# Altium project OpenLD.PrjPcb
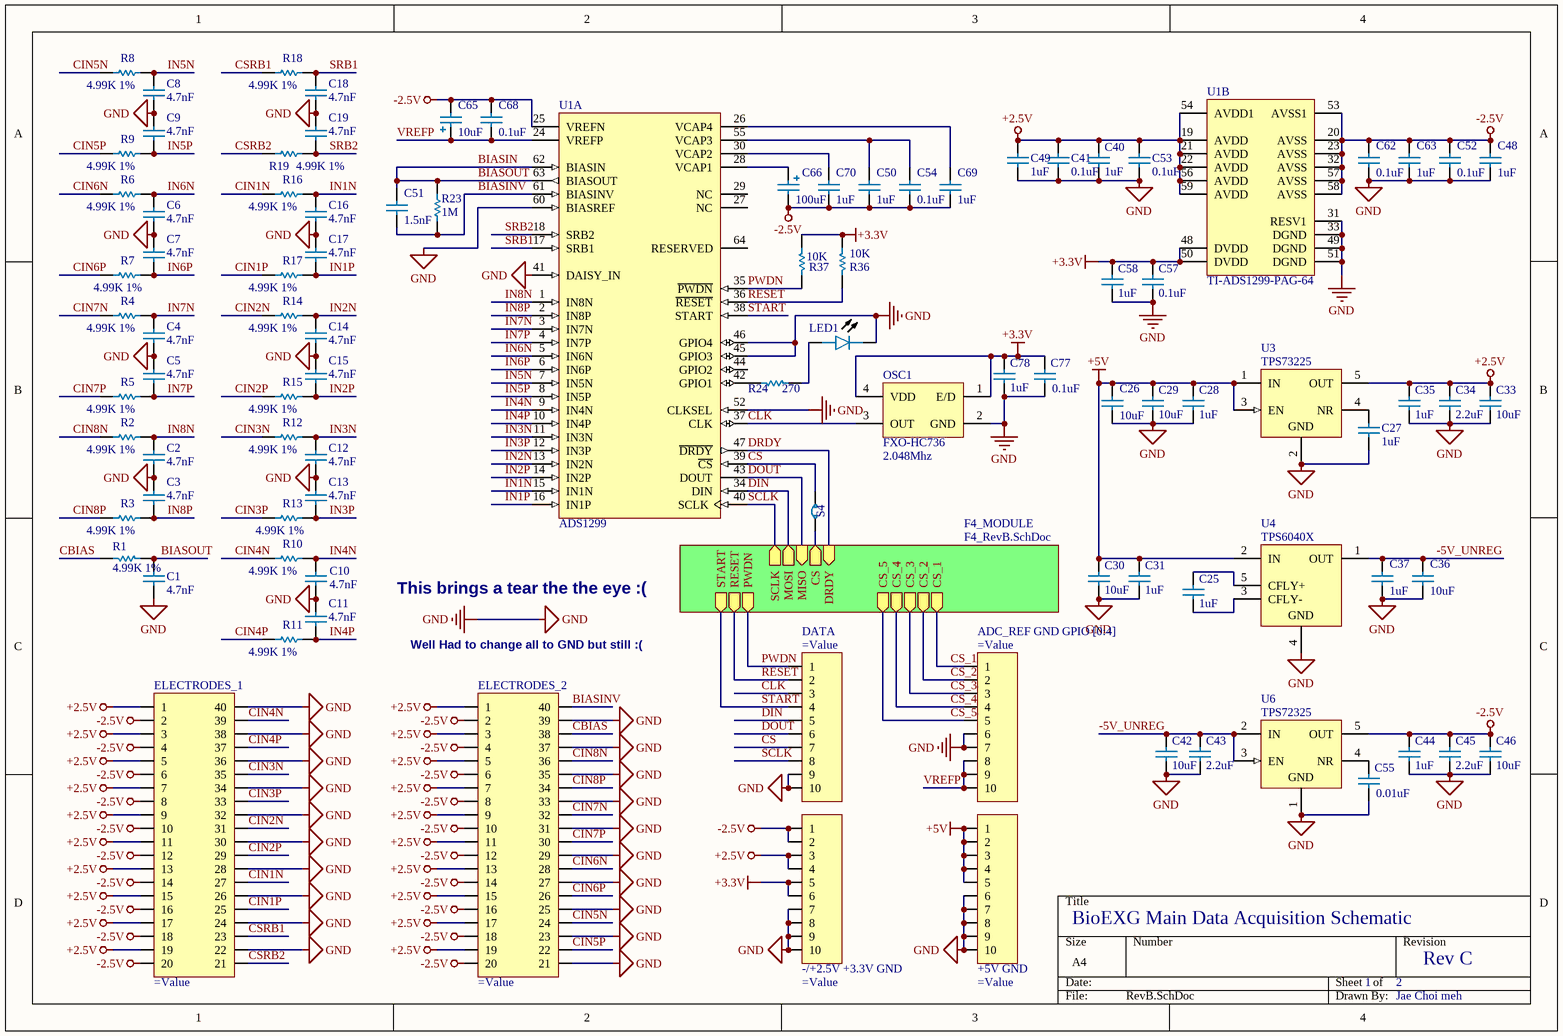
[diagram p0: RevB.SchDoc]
2 sheets, 147 parts. Net scope: hierarchical (ports join the sheet entries above them; power ports are global).
Board file: RevC.PcbDoc
Sheets:
  RevB.SchDoc
    F4_MODULE = F4_RevB.SchDoc

## Sheet RevB.SchDoc
size A4

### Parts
+5V_GND  (no value)  [M52-10]
-/+2.5V_+3.3V_GND  (no value)  [M52-10]
ADC_REF_GND_GPIO_[0:4]  (no value)  [M52-10]
C1  4.7nF  [C0603]
C2  4.7nF  [C0603]
C3  4.7nF  [C0603]
C4  4.7nF  [C0603]
C5  4.7nF  [C0603]
C6  4.7nF  [C0603]
C7  4.7nF  [C0603]
C8  4.7nF  [C0603]
C9  4.7nF  [C0603]
C10  4.7nF  [C0603]
C11  4.7nF  [C0603]
C12  4.7nF  [C0603]
C13  4.7nF  [C0603]
C14  4.7nF  [C0603]
C15  4.7nF  [C0603]
C16  4.7nF  [C0603]
C17  4.7nF  [C0603]
C18  4.7nF  [C0603]
C19  4.7nF  [C0603]
C25  1uF  [C0603]
C26  10uF  [C0603]
C27  1uF  [C0603]
C28  1uF  [C0603]
C29  10uF  [C0603]
C30  10uF  [C0603]
C31  1uF  [C0603]
C33  10uF  [C0603]
C34  2.2uF  [C0603]
C35  1uF  [C0603]
C36  10uF  [C0603]
C37  1uF  [C0603]
C40  1uF  [C0603]
C41  0.1uF  [C0603]
C42  10uF  [C0603]
C43  2.2uF  [C0603]
C44  1uF  [C0603]
C45  2.2uF  [C0603]
C46  10uF  [C0603]
C48  1uF  [C0603]
C49  1uF  [C0603]
C50  1uF  [C0603]
C51  1.5nF  [C0603]
C52  0.1uF  [C0603]
C53  0.1uF  [C0603]
C54  0.1uF  [C0603]
C55  0.01uF  [C0603]
C57  0.1uF  [C0603]
C58  1uF  [C0603]
C62  0.1uF  [C0603]
C63  1uF  [C0603]
C65  10uF  [TCAXM8R]
C66  100uF  [TCAXM8R]
C68  0.1uF  [C0603]
C69  1uF  [C0603]
C70  1uF  [C0603]
C77  0.1uF  [C0603]
C78  1uF  [C0603]
DATA  (no value)  [M52-10]
ELECTRODES_1  (no value)  [M50-40]
ELECTRODES_2  (no value)  [M50-40]
LED1  LSTS0603  [LITEON_LED_0603]  (value not drawn)
OSC1  FXO-HC736  value 2.048Mhz  [HC73]
R1  4.99K 1%  [ERA3A]
R2  4.99K 1%  [ERA3A]
R3  4.99K 1%  [ERA3A]
R4  4.99K 1%  [ERA3A]
R5  4.99K 1%  [ERA3A]
R6  4.99K 1%  [ERA3A]
R7  4.99K 1%  [ERA3A]
R8  4.99K 1%  [ERA3A]
R9  4.99K 1%  [ERA3A]
R10  4.99K 1%  [ERA3A]
R11  4.99K 1%  [ERA3A]
R12  4.99K 1%  [ERA3A]
R13  4.99K 1%  [ERA3A]
R14  4.99K 1%  [ERA3A]
R15  4.99K 1%  [ERA3A]
R16  4.99K 1%  [ERA3A]
R17  4.99K 1%  [ERA3A]
R18  4.99K 1%  [ERA3A]
R19  4.99K 1%  [ERA3A]
R23  1M  [ERA6A]
R24  270  [ERA3A]
R36  10K  [ERA3A]
R37  10K  [ERA3A]
S4  (no value)  [JUMPER]
U1  ADS1299  [TI-PAG64_N]  (parts A,B of 2)
U3  TPS73225  [TI-DBV5_N]
U4  TPS6040X  [TI-DBV5_N]
U6  TPS72325  [TI-DBV5_N]

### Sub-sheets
F4_MODULE = F4_RevB.SchDoc: PWDN (out), RESET (out), START (out), CS_5 (out), CS_4 (out), CS_3 (out), CS_2 (out), CS_1 (out), DRDY (in), CS (out), MISO (in), MOSI (out), SCLK (out)

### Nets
+2.5V: -/+2.5V_+3.3V_GND.3 -/+2.5V_+3.3V_GND.4 C33.2 C34.2 C35.2 C40.2 C41.1 C49.1 C53.1 ELECTRODES_1.1 ELECTRODES_1.3 ELECTRODES_1.5 ELECTRODES_1.7 ELECTRODES_1.9 ELECTRODES_1.11 ELECTRODES_1.13 ELECTRODES_1.15 ELECTRODES_1.17 ELECTRODES_1.19 ELECTRODES_2.1 ELECTRODES_2.3 ELECTRODES_2.5 ELECTRODES_2.7 ELECTRODES_2.9 ELECTRODES_2.11 ELECTRODES_2.13 ELECTRODES_2.15 ELECTRODES_2.17 ELECTRODES_2.19 U1.19(AVDD) U1.21(AVDD) U1.22(AVDD) U1.54(AVDD1) U1.56(AVDD) U1.59(AVDD) U3.5(OUT)
+3.3V: -/+2.5V_+3.3V_GND.5 -/+2.5V_+3.3V_GND.6 C57.2 C58.2 C77.2 C78.2 OSC1.1(E/D) OSC1.4(VDD) R36.2 R37.2 U1.48(DVDD) U1.50(DVDD)
+5V: +5V_GND.1 +5V_GND.2 +5V_GND.3 +5V_GND.4 +5V_GND.5 C26.1 C28.2 C29.2 C30.2 C31.2 U3.1(IN) U3.3(EN) U4.2(IN)
-2.5V: -/+2.5V_+3.3V_GND.1 -/+2.5V_+3.3V_GND.2 C44.2 C45.2 C46.2 C48.1 C50.2 C52.1 C54.2 C62.1 C63.1 C65.2 C66.2 C68.2 C69.2 C70.2 ELECTRODES_1.2 ELECTRODES_1.4 ELECTRODES_1.6 ELECTRODES_1.8 ELECTRODES_1.10 ELECTRODES_1.12 ELECTRODES_1.14 ELECTRODES_1.16 ELECTRODES_1.18 ELECTRODES_1.20 ELECTRODES_2.2 ELECTRODES_2.4 ELECTRODES_2.6 ELECTRODES_2.8 ELECTRODES_2.10 ELECTRODES_2.12 ELECTRODES_2.14 ELECTRODES_2.16 ELECTRODES_2.18 ELECTRODES_2.20 U1.20(AVSS) U1.23(AVSS) U1.25(VREFN) U1.32(AVSS) U1.53(AVSS1) U1.57(AVSS) U1.58(AVSS) U6.5(OUT)
GND: +5V_GND.6 +5V_GND.7 +5V_GND.8 +5V_GND.9 +5V_GND.10 -/+2.5V_+3.3V_GND.7 -/+2.5V_+3.3V_GND.8 -/+2.5V_+3.3V_GND.9 -/+2.5V_+3.3V_GND.10 ADC_REF_GND_GPIO_[0:4].6 ADC_REF_GND_GPIO_[0:4].7 C1.2 C2.2 C3.2 C4.2 C5.2 C6.2 C7.2 C8.2 C9.2 C10.2 C11.2 C12.2 C13.2 C14.2 C15.2 C16.2 C17.2 C18.2 C19.2 C26.2 C27.2 C28.1 C29.1 C30.1 C31.1 C33.1 C34.1 C35.1 C36.2 C37.2 C40.1 C41.2 C42.1 C43.1 C44.1 C45.1 C46.1 C48.2 C49.2 C52.2 C53.2 C55.1 C57.1 C58.1 C62.2 C63.2 C77.1 C78.1 DATA.9 DATA.10 ELECTRODES_1.22 ELECTRODES_1.24 ELECTRODES_1.26 ELECTRODES_1.28 ELECTRODES_1.30 ELECTRODES_1.32 ELECTRODES_1.34 ELECTRODES_1.36 ELECTRODES_1.38 ELECTRODES_1.40 ELECTRODES_2.21 ELECTRODES_2.23 ELECTRODES_2.25 ELECTRODES_2.27 ELECTRODES_2.29 ELECTRODES_2.31 ELECTRODES_2.33 ELECTRODES_2.35 ELECTRODES_2.37 ELECTRODES_2.39 LED1.2(K) OSC1.2(GND) U1.31(RESV1) U1.33(DGND) U1.41(DAISY_IN) U1.45(GPIO3) U1.46(GPIO4) U1.49(DGND) U1.51(DGND) U1.52(CLKSEL) U1.60(BIASREF) U3.2(GND) U4.4(GND) U6.1(GND)
-5V_UNREG: C36.1 C37.1 C42.2 C43.2 U4.1(OUT) U6.2(IN) U6.3(EN)
BIASIN: C1.1 C51.1 R1.2 R23.1 U1.62(BIASIN) U1.63(BIASOUT)  [also labelled BIASOUT]
BIASINV: C51.2 ELECTRODES_2.40 R23.2 U1.61(BIASINV)
CBIAS: ELECTRODES_2.38 R1.1
CIN1N: ELECTRODES_1.27 R16.1
CIN1P: ELECTRODES_1.25 R17.1
CIN2N: ELECTRODES_1.31 R14.1
CIN2P: ELECTRODES_1.29 R15.1
CIN3N: ELECTRODES_1.35 R12.1
CIN3P: ELECTRODES_1.33 R13.1
CIN4N: ELECTRODES_1.39 R10.1
CIN4P: ELECTRODES_1.37 R11.1
CIN5N: ELECTRODES_2.24 R8.1
CIN5P: ELECTRODES_2.22 R9.1
CIN6N: ELECTRODES_2.28 R6.1
CIN6P: ELECTRODES_2.26 R7.1
CIN7N: ELECTRODES_2.32 R4.1
CIN7P: ELECTRODES_2.30 R5.1
CIN8N: ELECTRODES_2.36 R2.1
CIN8P: ELECTRODES_2.34 R3.1
CLK: DATA.3 OSC1.3(OUT) U1.37(CLK)
CS: DATA.7 S4.2 U1.39(~{CS})
CS_1: ADC_REF_GND_GPIO_[0:4].1 ; sheet F4_MODULE/CS_1
CS_2: ADC_REF_GND_GPIO_[0:4].2 ; sheet F4_MODULE/CS_2
CS_3: ADC_REF_GND_GPIO_[0:4].3 ; sheet F4_MODULE/CS_3
CS_4: ADC_REF_GND_GPIO_[0:4].4 ; sheet F4_MODULE/CS_4
CS_5: ADC_REF_GND_GPIO_[0:4].5 ; sheet F4_MODULE/CS_5
CSRB1: ELECTRODES_1.23 R18.1
CSRB2: ELECTRODES_1.21 R19.1
DIN: DATA.5 U1.34(DIN) ; sheet F4_MODULE/MOSI
DOUT: DATA.6 U1.43(DOUT) ; sheet F4_MODULE/MISO
DRDY: U1.47(~{DRDY}) ; sheet F4_MODULE/DRDY
IN1N: C16.1 R16.2 U1.15(IN1N)
IN1P: C17.1 R17.2 U1.16(IN1P)
IN2N: C14.1 R14.2 U1.13(IN2N)
IN2P: C15.1 R15.2 U1.14(IN2P)
IN3N: C12.1 R12.2 U1.11(IN3N)
IN3P: C13.1 R13.2 U1.12(IN3P)
IN4N: C10.1 R10.2 U1.9(IN4N)
IN4P: C11.1 R11.2 U1.10(IN4P)
IN5N: C8.1 R8.2 U1.7(IN5N)
IN5P: C9.1 R9.2 U1.8(IN5P)
IN6N: C6.1 R6.2 U1.5(IN6N)
IN6P: C7.1 R7.2 U1.6(IN6P)
IN7N: C4.1 R4.2 U1.3(IN7N)
IN7P: C5.1 R5.2 U1.4(IN7P)
IN8N: C2.1 R2.2 U1.1(IN8N)
IN8P: C3.1 R3.2 U1.2(IN8P)
PD7: S4.1 ; sheet F4_MODULE/CS
PWDN: DATA.1 R37.1 U1.35(~{PWDN}) ; sheet F4_MODULE/PWDN  [project net PB8]
RESET: DATA.2 R36.1 U1.36(~{RESET}) ; sheet F4_MODULE/RESET  [project net PB7]
SCLK: DATA.8 U1.40(SCLK) ; sheet F4_MODULE/SCLK  [project net PB3]
SRB1: C18.1 R18.2 U1.17(SRB1)
SRB2: C19.1 R19.2 U1.18(SRB2)
START: DATA.4 U1.38(START) ; sheet F4_MODULE/START  [project net PB6]
VREFP: ADC_REF_GND_GPIO_[0:4].8 ADC_REF_GND_GPIO_[0:4].9 ADC_REF_GND_GPIO_[0:4].10 C65.1 C68.1 U1.24(VREFP)
NetC25_1: C25.1 U4.3(CFLY-)
NetC25_2: C25.2 U4.5(CFLY+)
NetC27_1: C27.1 U3.4(NR)
NetC50_1: C50.1 C54.1 U1.55(VCAP3)
NetC55_2: C55.2 U6.4(NR)
NetC66_1: C66.1 U1.28(VCAP1)
NetC69_1: C69.1 U1.26(VCAP4)
NetC70_1: C70.1 U1.30(VCAP2)
NetLED1_1: LED1.1(A) R24.2
NetR24_1: R24.1 U1.42(GPIO1)

Not connected (* = marked no-connect by the designer): U1 27(NC) 29(NC) 44(GPIO2) 64(RESERVED)

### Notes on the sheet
- This brings a tear the the eye :(
- Well Had to change all to GND but still :(
- BioEXG Main Data Acquisition Schematic
- 1
- 2
- Rev C
- Jae Choi meh

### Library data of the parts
+5V_GND -/+2.5V_+3.3V_GND ADC_REF_GND_GPIO_[0:4] DATA = M52-10: M52 Series Female Header Connector
C1-C19 C25-C31 C33-C37 C40-C46 C48-C55 C57 C58 C62 C63 C68-C70 C77 C78 = CAP: Capacitor Non Polarized
C65 C66 = CAP_POL: Polarized Capacitor - Tantalum
ELECTRODES_1 ELECTRODES_2 = M50-40: M50 Series Female Header Connector
LED1 = LITEON LED: LITE ON LED 0603
OSC1 = FXO-HC73: FXO-HC73 Series Oscillator; Manufacturer: Fox Electronics; Manufacturer Part Number: FXO-HC736R-2.048; Current - Supply (Max): 32mA; Frequency Stability: ±25ppm; Function: Tri-State (Output Enable); Output: HCMOS; Voltage - Supply: 3.3V
R1-R19 R23 R24 R36 R37 = RES: Resistor
S4 = JMP: Jumper
U1 = TI-ADS1299-PAG-64: The Famous ADS1299 :)
U3 = TI-TPS73225-DVB5: TPS73225/TPS73233 Voltage Regulator
U4 = TI-TPS6040X-DBV5: TPS6040X Voltage Inverter
U6 = TI-TPS72325-DBV5: TPS72325 Negative Voltage Regulator

## Sheet F4_RevB.SchDoc
size A4
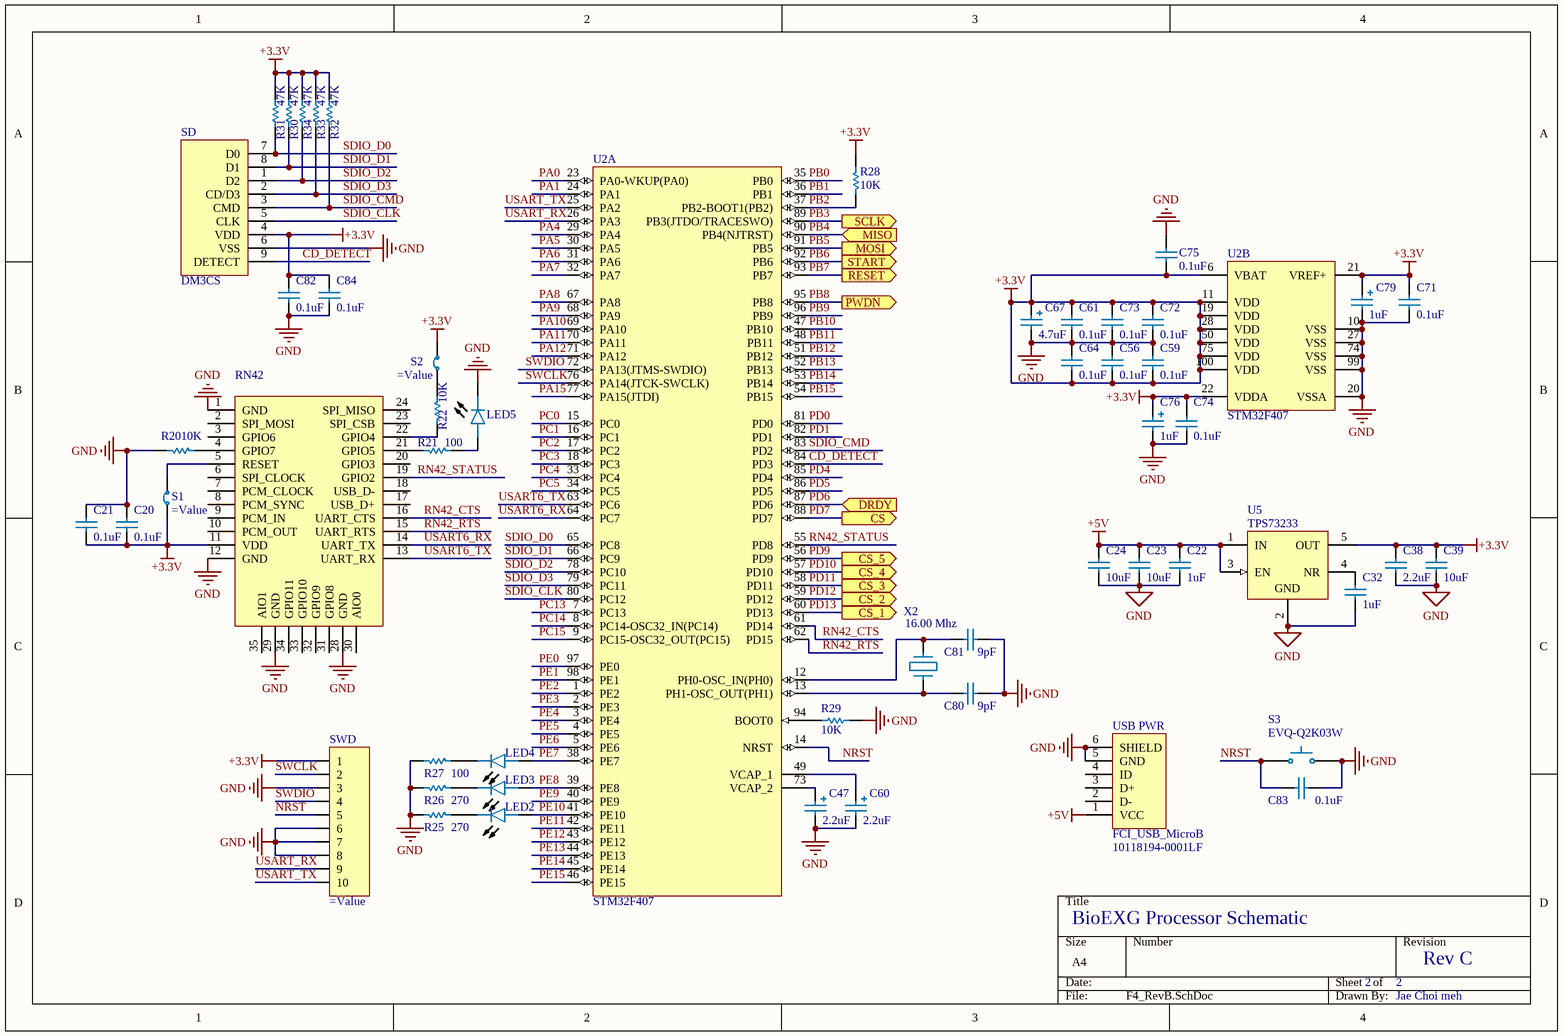
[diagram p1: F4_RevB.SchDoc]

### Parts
C20  0.1uF  [C0603]
C21  0.1uF  [C0603]
C22  1uF  [C0603]
C23  10uF  [C0603]
C24  10uF  [C0603]
C32  1uF  [C0603]
C38  2.2uF  [C0603]
C39  10uF  [C0603]
C47  2.2uF  [TCAXM8R]
C56  0.1uF  [C0603]
C59  0.1uF  [C0603]
C60  2.2uF  [TCAXM8R]
C61  0.1uF  [C0603]
C64  0.1uF  [C0603]
C67  4.7uF  [TCAXM8R]
C71  0.1uF  [C0603]
C72  0.1uF  [C0603]
C73  0.1uF  [C0603]
C74  0.1uF  [C0603]
C75  0.1uF  [C0603]
C76  1uF  [TCAXM8R]
C79  1uF  [TCAXM8R]
C80  9pF  [C0603]
C81  9pF  [C0603]
C82  0.1uF  [C0603]
C83  0.1uF  [C0603]
C84  0.1uF  [C0603]
LED2  LSTS0603  [LITEON_LED_0603]  (value not drawn)
LED3  LSTS0603  [LITEON_LED_0603]  (value not drawn)
LED4  LSTS0603  [LITEON_LED_0603]  (value not drawn)
LED5  LSTS0603  [LITEON_LED_0603]  (value not drawn)
R20  10K  [ERA3A]
R21  100  [ERA3A]
R22  10K  [ERA3A]
R25  270  [ERA3A]
R26  270  [ERA3A]
R27  100  [ERA3A]
R28  10K  [ERA3A]
R29  10K  [ERA3A]
R30  47K  [ERA3A]
R31  47K  [ERA3A]
R32  47K  [ERA3A]
R33  47K  [ERA3A]
R34  47K  [ERA3A]
RN42  RN42  [RN42]  (value not drawn)
S1  (no value)  [JUMPER]
S2  (no value)  [JUMPER]
S3  Manufacturer Part Number: EVQ-Q2K03W  [EVQQ2]  (hidden comment: EVQQ2)
SD  DM3CS  [DM3CS]
SWD  (no value)  [M52-10]
U2  STM32F407  [STM-LQFP100_N]  (parts A,B of 2)
U5  TPS73233  [TI-DBV5_N]
USB_PWR  FCI_USB_MicroB  Manufacturer Part Number: 10118194-0001LF  [USB_Micro_B]
X2  16.00 Mhz  [405XO]

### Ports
CS (out), CS_1 (out), CS_2 (out), CS_3 (out), CS_4 (out), CS_5 (out), DRDY (in), MISO (in), MOSI (out), PWDN (out), RESET (out), SCLK (out), START (out)

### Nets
+3.3V: C20.2 C21.2 C38.2 C39.2 C56.2 C59.1 C61.2 C64.2 C67.1 C71.2 C72.2 C73.2 C74.2 C75.2 C76.1 C79.1 C82.1 C84.1 R28.1 R30.1 R31.1 R32.1 R33.1 R34.1 RN42.11(VDD) S1.1 S2.2 SD.4(VDD) SWD.1 U2.6(VBAT) U2.11(VDD) U2.19(VDD) U2.21(VREF+) U2.22(VDDA) U2.28(VDD) U2.50(VDD) U2.75(VDD) U2.100(VDD) U5.5(OUT)
+5V: C22.2 C23.2 C24.2 U5.1(IN) U5.3(EN) USB_PWR.1(VCC)
GND: C20.1 C21.1 C22.1 C23.1 C24.1 C32.1 C38.1 C39.1 C47.2 C56.1 C59.2 C60.2 C61.1 C64.1 C67.2 C71.1 C72.1 C73.1 C74.1 C75.1 C76.2 C79.2 C80.2 C81.2 C82.2 C83.2 C84.2 LED5.2(K) R20.2 R25.2 R26.2 R27.2 R29.1 RN42.1(GND) RN42.12(GND) RN42.28(GND) RN42.29(GND) S3.B SD.6(VSS) SWD.3 SWD.6 SWD.7 SWD.8 U2.10(VSS) U2.20(VSSA) U2.27(VSS) U2.74(VSS) U2.99(VSS) U5.2(GND) USB_PWR.5(GND) USB_PWR.6(SHIELD)
CD_DETECT: SD.9(DETECT) U2.84(PD3)
NRST: C83.1 S3.A SWD.5 U2.14(NRST)
PA0: U2.23(PA0-WKUP(PA0))
PA1: U2.24(PA1)
PA4: U2.29(PA4)
PA5: U2.30(PA5)
PA6: U2.31(PA6)
PA7: U2.32(PA7)
PA8: U2.67(PA8)
PA9: U2.68(PA9)
PA10: U2.69(PA10)
PA11: U2.70(PA11)
PA12: U2.71(PA12)
PA15: U2.77(PA15(JTDI))
PB0: U2.35(PB0)
PB1: U2.36(PB1)
PB2: R28.2 U2.37(PB2-BOOT1(PB2))
PB3: U2.89(PB3(JTDO/TRACESWO)) ; port SCLK
PB4: U2.90(PB4(NJTRST)) ; port MISO  [project net DOUT]
PB5: U2.91(PB5) ; port MOSI  [project net DIN]
PB6: U2.92(PB6) ; port START
PB7: U2.93(PB7) ; port RESET
PB8: U2.95(PB8) ; port PWDN
PB9: U2.96(PB9)
PB10: U2.47(PB10)
PB11: U2.48(PB11)
PB12: U2.51(PB12)
PB13: U2.52(PB13)
PB14: U2.53(PB14)
PB15: U2.54(PB15)
PC0: U2.15(PC0)
PC1: U2.16(PC1)
PC2: U2.17(PC2)
PC3: U2.18(PC3)
PC4: U2.33(PC4)
PC5: U2.34(PC5)
PC13: U2.7(PC13)
PC14: U2.8(PC14-OSC32_IN(PC14))
PC15: U2.9(PC15-OSC32_OUT(PC15))
PD0: U2.81(PD0)
PD1: U2.82(PD1)
PD4: U2.85(PD4)
PD5: U2.86(PD5)
PD6: U2.87(PD6) ; port DRDY  [project net DRDY]
PD7: U2.88(PD7) ; port CS
PD9: U2.56(PD9) ; port CS_5  [project net CS_5]
PD10: U2.57(PD10) ; port CS_4  [project net CS_4]
PD11: U2.58(PD11) ; port CS_3  [project net CS_3]
PD12: U2.59(PD12) ; port CS_2  [project net CS_2]
PD13: U2.60(PD13) ; port CS_1  [project net CS_1]
PE0: U2.97(PE0)
PE1: U2.98(PE1)
PE2: U2.1(PE2)
PE3: U2.2(PE3)
PE4: U2.3(PE4)
PE5: U2.4(PE5)
PE6: U2.5(PE6)
PE7: LED4.1(A) U2.38(PE7)
PE8: LED3.1(A) U2.39(PE8)
PE9: U2.40(PE9)
PE10: LED2.1(A) U2.41(PE10)
PE11: U2.42(PE11)
PE12: U2.43(PE12)
PE13: U2.44(PE13)
PE14: U2.45(PE14)
PE15: U2.46(PE15)
RN42_CTS: RN42.16(UART_CTS) U2.61(PD14)
RN42_RTS: RN42.15(UART_RTS) U2.62(PD15)
RN42_STATUS: RN42.19(GPIO2) U2.55(PD8)
SDIO_CLK: SD.5(CLK) U2.80(PC12)
SDIO_CMD: R32.2 SD.3(CMD) U2.83(PD2)
SDIO_D0: R31.2 SD.7(D0) U2.65(PC8)
SDIO_D1: R30.2 SD.8(D1) U2.66(PC9)
SDIO_D2: R34.2 SD.1(D2) U2.78(PC10)
SDIO_D3: R33.2 SD.2(CD/D3) U2.79(PC11)
SWCLK: SWD.2 U2.76(PA14(JTCK-SWCLK))
SWDIO: SWD.4 U2.72(PA13(JTMS-SWDIO))
USART6_RX: RN42.14(UART_TX) U2.64(PC7)
USART6_TX: RN42.13(UART_RX) U2.63(PC6)
USART_RX: SWD.9 U2.26(PA3)
USART_TX: SWD.10 U2.25(PA2)
NetC32_2: C32.2 U5.4(NR)
NetC47_1: C47.1 U2.73(VCAP_2)
NetC60_1: C60.1 U2.49(VCAP_1)
NetC80_1: C80.1 U2.13(PH1-OSC_OUT(PH1)) X2.1
NetC81_1: C81.1 U2.12(PH0-OSC_IN(PH0)) X2.3
NetLED2_2: LED2.2(K) R25.1
NetLED3_2: LED3.2(K) R26.1
NetLED4_2: LED4.2(K) R27.1
NetLED5_1: LED5.1(A) R21.1
NetR20_1: R20.1 RN42.4(GPIO7)
NetR21_2: R21.2 RN42.21(GPIO5)
NetR22_1: R22.1 RN42.22(GPIO4)
NetR22_2: R22.2 S2.1
NetR29_2: R29.2 U2.94(BOOT0)
NetRN42_5: RN42.5(RESET) S1.2

Not connected (* = marked no-connect by the designer): RN42 2(SPI_MOSI) 3(GPIO6) 6(SPI_CLOCK) 7(PCM_CLOCK) 8(PCM_SYNC) 9(PCM_IN) 10(PCM_OUT) 17(USB_D+) 18(USB_D-) 20(GPIO3) 23(SPI_CSB) 24(SPI_MISO) 30(AIO0) 31(GPIO8) 32(GPIO9) 33(GPIO10) 34(GPIO11) 35(AIO1); USB_PWR 2(D-) 3(D+) 4(ID)

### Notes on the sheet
- BioEXG Processor Schematic
- 2
- Rev C
- Jae Choi meh

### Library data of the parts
C20-C24 C32 C38 C39 C56 C59 C61 C64 C71-C75 C80-C84 = CAP: Capacitor Non Polarized
C47 C60 C67 C76 C79 = CAP_POL: Polarized Capacitor - Tantalum
LED2-LED5 = LITEON LED: LITE ON LED 0603
R20-R22 R25-R34 = RES: Resistor
RN42 = RN42: RN42 Bluetooth Transciever
S1 S2 = JMP: Jumper
S3 = EVQQ2 Tactile Button: Manufacturer: Panasonic Electronic Components; Circuit: SPST-NO; Switch Function: Off-Mom; Contact Rating @ Voltage: 0.02A @ 15VDC; Actuator Type: Standard; Actuator Height off PCB, from Pins: 3.10mm; Actuator Orientation: Top Actuated; Outline: 6.60mm x 6.00mm; Illumination: Non-Illuminated; Operating Force: 130gf; Switch Travel: 0.25mm; Mechanical Life: 1,000,000 Cycles
SD = DM3CS: DM3CS Micro SD Card Holder
SWD = M52-10: M52 Series Female Header Connector
U2 = STM32F407: STM32F407 32 bit Microcontroller
U5 = TI-TPS73225-DVB5: TPS73225/TPS73233 Voltage Regulator
USB_PWR = FCI_USB_MicroB: FCI USB Micro B; Connector Type: USB - micro B; Number of Contacts: 5; Gender: Receptacle; Specifications: USB 2.0
X2 = CTS-405: CTS 405 Series Crystal Oscillator

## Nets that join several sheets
+3.3V: RevB (12 pins), F4_RevB (39 pins)
+5V: RevB (13 pins), F4_RevB (6 pins)
GND: RevB (95 pins), F4_RevB (51 pins)
CS_1: RevB (ADC_REF_GND_GPIO_[0:4].1), F4_RevB (U2.60)
CS_2: RevB (ADC_REF_GND_GPIO_[0:4].2), F4_RevB (U2.59)
CS_3: RevB (ADC_REF_GND_GPIO_[0:4].3), F4_RevB (U2.58)
CS_4: RevB (ADC_REF_GND_GPIO_[0:4].4), F4_RevB (U2.57)
CS_5: RevB (ADC_REF_GND_GPIO_[0:4].5), F4_RevB (U2.56)
DIN: RevB (DATA.5 U1.34), F4_RevB (U2.91)
DOUT: RevB (DATA.6 U1.43), F4_RevB (U2.90)
DRDY: RevB (U1.47), F4_RevB (U2.87)
PB3: RevB (DATA.8 U1.40), F4_RevB (U2.89)
PB6: RevB (DATA.4 U1.38), F4_RevB (U2.92)
PB7: RevB (DATA.2 R36.1 U1.36), F4_RevB (U2.93)
PB8: RevB (DATA.1 R37.1 U1.35), F4_RevB (U2.95)
PD7: RevB (S4.1), F4_RevB (U2.88)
